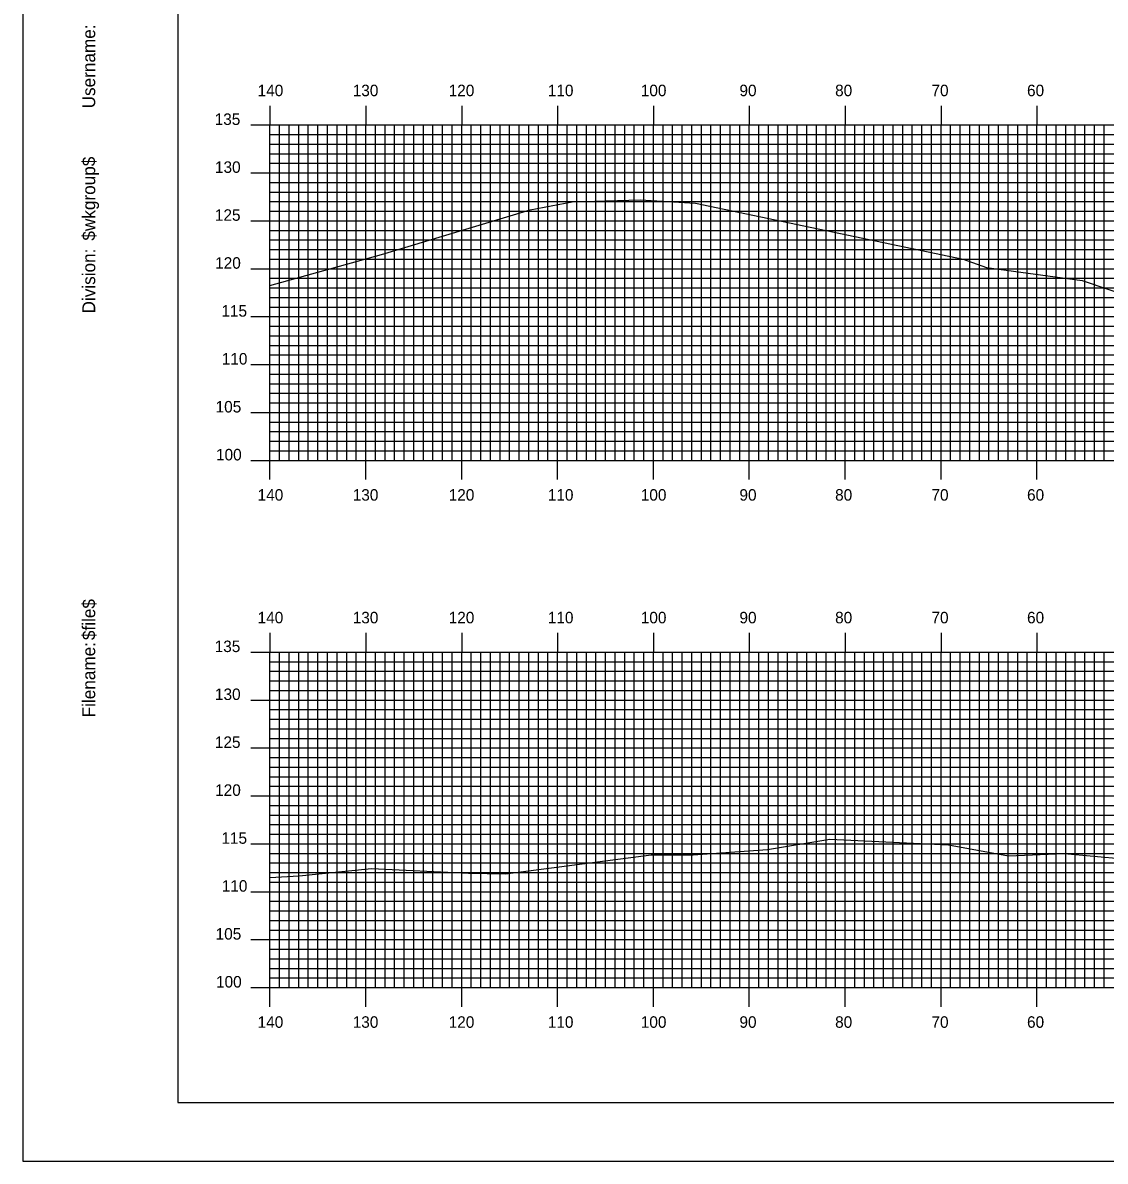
# Model space of a CAD drawing. Extents: x 1766513 to 1766856, y 442591 to 442811.
# Drawn here: x 1766513.1 to 1766626, y 442590.5 to 442709.3 of the extents above; entities that cross this region are included whole.
import ezdxf

# ---------------------------------------------------------------- set-up
doc = ezdxf.new("R2010")
doc.units = 0
for name, color, linetype in [('BORDER', 7, 'Continuous'), ('H_V ANNOTATION', 7, 'Continuous'), ('MAJOR', 7, 'Continuous'), ('MINOR', 7, 'Continuous'), ('PLOT BOUNDARY', 7, 'Continuous'), ('S_Roadway_Centerline', 7, 'Continuous')]:
    doc.layers.add(name, color=color, linetype=linetype)

msp = doc.modelspace()

# ---------------------------------------------------------------- linework, layer by layer
at = {"layer": 'BORDER'}
msp.add_lwpolyline([(1766529.31, 442596.67), (1766849.31, 442596.67), (1766849.31, 442806.67), (1766529.31, 442806.67)], close=True, dxfattribs=at)
at = {"layer": 'MAJOR'}
for p, q in [((1766538.91, 442700.67), (1766538.91, 442698.67)), ((1766548.91, 442700.67), (1766548.91, 442698.67)), ((1766558.91, 442700.67), (1766558.91, 442698.67)), ((1766568.91, 442700.67), (1766568.91, 442698.67)), ((1766578.91, 442700.67), (1766578.91, 442698.67)), ((1766588.91, 442700.67), (1766588.91, 442698.67)), ((1766598.91, 442700.67), (1766598.91, 442698.67)), ((1766608.91, 442700.67), (1766608.91, 442698.67)), ((1766618.91, 442700.67), (1766618.91, 442698.67)), ((1766536.91, 442698.67), (1766538.91, 442698.67)), ((1766538.91, 442698.67), (1766818.91, 442698.67)), ((1766538.91, 442663.67), (1766538.91, 442698.67)), ((1766538.91, 442663.67), (1766538.91, 442698.67)), ((1766538.91, 442698.67), (1766818.91, 442698.67)), ((1766548.91, 442663.67), (1766548.91, 442698.67)), ((1766558.91, 442663.67), (1766558.91, 442698.67)), ((1766568.91, 442663.67), (1766568.91, 442698.67)), ((1766578.91, 442663.67), (1766578.91, 442698.67)), ((1766588.91, 442663.67), (1766588.91, 442698.67)), ((1766598.91, 442663.67), (1766598.91, 442698.67)), ((1766608.91, 442663.67), (1766608.91, 442698.67)), ((1766618.91, 442663.67), (1766618.91, 442698.67)), ((1766536.91, 442693.67), (1766538.91, 442693.67)), ((1766538.91, 442693.67), (1766818.91, 442693.67)), ((1766536.91, 442688.67), (1766538.91, 442688.67)), ((1766538.91, 442688.67), (1766818.91, 442688.67)), ((1766536.91, 442683.67), (1766538.91, 442683.67)), ((1766538.91, 442683.67), (1766818.91, 442683.67)), ((1766536.91, 442678.67), (1766538.91, 442678.67)), ((1766538.91, 442678.67), (1766818.91, 442678.67)), ((1766536.91, 442673.67), (1766538.91, 442673.67)), ((1766538.91, 442673.67), (1766818.91, 442673.67)), ((1766536.91, 442668.67), (1766538.91, 442668.67)), ((1766538.91, 442668.67), (1766818.91, 442668.67)), ((1766536.91, 442663.67), (1766538.91, 442663.67)), ((1766538.91, 442663.67), (1766818.91, 442663.67)), ((1766538.91, 442663.67), (1766818.91, 442663.67)), ((1766538.91, 442661.66), (1766538.91, 442663.67)), ((1766548.91, 442661.66), (1766548.91, 442663.67)), ((1766558.91, 442661.66), (1766558.91, 442663.67)), ((1766568.91, 442661.66), (1766568.91, 442663.67)), ((1766578.91, 442661.66), (1766578.91, 442663.67)), ((1766588.91, 442661.66), (1766588.91, 442663.67)), ((1766598.91, 442661.66), (1766598.91, 442663.67)), ((1766608.91, 442661.66), (1766608.91, 442663.67)), ((1766618.91, 442661.66), (1766618.91, 442663.67)), ((1766538.91, 442645.67), (1766538.91, 442643.67)), ((1766548.91, 442645.67), (1766548.91, 442643.67)), ((1766558.91, 442645.67), (1766558.91, 442643.67)), ((1766568.91, 442645.67), (1766568.91, 442643.67)), ((1766578.91, 442645.67), (1766578.91, 442643.67)), ((1766588.91, 442645.67), (1766588.91, 442643.67)), ((1766598.91, 442645.67), (1766598.91, 442643.67)), ((1766608.91, 442645.67), (1766608.91, 442643.67)), ((1766618.91, 442645.67), (1766618.91, 442643.67)), ((1766536.91, 442643.67), (1766538.91, 442643.67)), ((1766538.91, 442643.67), (1766818.91, 442643.67)), ((1766538.91, 442608.67), (1766538.91, 442643.67)), ((1766538.91, 442608.67), (1766538.91, 442643.67)), ((1766538.91, 442643.67), (1766818.91, 442643.67)), ((1766548.91, 442608.67), (1766548.91, 442643.67)), ((1766558.91, 442608.67), (1766558.91, 442643.67)), ((1766568.91, 442608.67), (1766568.91, 442643.67)), ((1766578.91, 442608.67), (1766578.91, 442643.67)), ((1766588.91, 442608.67), (1766588.91, 442643.67)), ((1766598.91, 442608.67), (1766598.91, 442643.67)), ((1766608.91, 442608.67), (1766608.91, 442643.67)), ((1766618.91, 442608.67), (1766618.91, 442643.67)), ((1766536.91, 442638.67), (1766538.91, 442638.67)), ((1766538.91, 442638.67), (1766818.91, 442638.67)), ((1766536.91, 442633.67), (1766538.91, 442633.67)), ((1766538.91, 442633.67), (1766818.91, 442633.67)), ((1766536.91, 442628.67), (1766538.91, 442628.67)), ((1766538.91, 442628.67), (1766818.91, 442628.67)), ((1766536.91, 442623.67), (1766538.91, 442623.67)), ((1766538.91, 442623.67), (1766818.91, 442623.67)), ((1766536.91, 442618.67), (1766538.91, 442618.67)), ((1766538.91, 442618.67), (1766818.91, 442618.67)), ((1766536.91, 442613.67), (1766538.91, 442613.67)), ((1766538.91, 442613.67), (1766818.91, 442613.67)), ((1766536.91, 442608.67), (1766538.91, 442608.67)), ((1766538.91, 442608.67), (1766818.91, 442608.67)), ((1766538.91, 442608.67), (1766818.91, 442608.67)), ((1766538.91, 442606.66), (1766538.91, 442608.67)), ((1766548.91, 442606.66), (1766548.91, 442608.67)), ((1766558.91, 442606.66), (1766558.91, 442608.67)), ((1766568.91, 442606.66), (1766568.91, 442608.67)), ((1766578.91, 442606.66), (1766578.91, 442608.67)), ((1766588.91, 442606.66), (1766588.91, 442608.67)), ((1766598.91, 442606.66), (1766598.91, 442608.67)), ((1766608.91, 442606.66), (1766608.91, 442608.67)), ((1766618.91, 442606.66), (1766618.91, 442608.67))]:
    msp.add_line(p, q, dxfattribs=at)
at = {"layer": 'MINOR'}
for p, q in [((1766539.91, 442663.67), (1766539.91, 442698.67)), ((1766540.91, 442663.67), (1766540.91, 442698.67)), ((1766541.91, 442663.67), (1766541.91, 442698.67)), ((1766542.91, 442663.67), (1766542.91, 442698.67)), ((1766543.91, 442663.67), (1766543.91, 442698.67)), ((1766544.91, 442663.67), (1766544.91, 442698.67)), ((1766545.91, 442663.67), (1766545.91, 442698.67)), ((1766546.91, 442663.67), (1766546.91, 442698.67)), ((1766547.91, 442663.67), (1766547.91, 442698.67)), ((1766549.91, 442663.67), (1766549.91, 442698.67)), ((1766550.91, 442663.67), (1766550.91, 442698.67)), ((1766551.91, 442663.67), (1766551.91, 442698.67)), ((1766552.91, 442663.67), (1766552.91, 442698.67)), ((1766553.91, 442663.67), (1766553.91, 442698.67)), ((1766554.91, 442663.67), (1766554.91, 442698.67)), ((1766555.91, 442663.67), (1766555.91, 442698.67)), ((1766556.91, 442663.67), (1766556.91, 442698.67)), ((1766557.91, 442663.67), (1766557.91, 442698.67)), ((1766559.91, 442663.67), (1766559.91, 442698.67)), ((1766560.91, 442663.67), (1766560.91, 442698.67)), ((1766561.91, 442663.67), (1766561.91, 442698.67)), ((1766562.91, 442663.67), (1766562.91, 442698.67)), ((1766563.91, 442663.67), (1766563.91, 442698.67)), ((1766564.91, 442663.67), (1766564.91, 442698.67)), ((1766565.91, 442663.67), (1766565.91, 442698.67)), ((1766566.91, 442663.67), (1766566.91, 442698.67)), ((1766567.91, 442663.67), (1766567.91, 442698.67)), ((1766569.91, 442663.67), (1766569.91, 442698.67)), ((1766570.91, 442663.67), (1766570.91, 442698.67)), ((1766571.91, 442663.67), (1766571.91, 442698.67)), ((1766572.91, 442663.67), (1766572.91, 442698.67)), ((1766573.91, 442663.67), (1766573.91, 442698.67)), ((1766574.91, 442663.67), (1766574.91, 442698.67)), ((1766575.91, 442663.67), (1766575.91, 442698.67)), ((1766576.91, 442663.67), (1766576.91, 442698.67)), ((1766577.91, 442663.67), (1766577.91, 442698.67)), ((1766579.91, 442663.67), (1766579.91, 442698.67)), ((1766580.91, 442663.67), (1766580.91, 442698.67)), ((1766581.91, 442663.67), (1766581.91, 442698.67)), ((1766582.91, 442663.67), (1766582.91, 442698.67)), ((1766583.91, 442663.67), (1766583.91, 442698.67)), ((1766584.91, 442663.67), (1766584.91, 442698.67)), ((1766585.91, 442663.67), (1766585.91, 442698.67)), ((1766586.91, 442663.67), (1766586.91, 442698.67)), ((1766587.91, 442663.67), (1766587.91, 442698.67)), ((1766589.91, 442663.67), (1766589.91, 442698.67)), ((1766590.91, 442663.67), (1766590.91, 442698.67)), ((1766591.91, 442663.67), (1766591.91, 442698.67)), ((1766592.91, 442663.67), (1766592.91, 442698.67)), ((1766593.91, 442663.67), (1766593.91, 442698.67)), ((1766594.91, 442663.67), (1766594.91, 442698.67)), ((1766595.91, 442663.67), (1766595.91, 442698.67)), ((1766596.91, 442663.67), (1766596.91, 442698.67)), ((1766597.91, 442663.67), (1766597.91, 442698.67)), ((1766599.91, 442663.67), (1766599.91, 442698.67)), ((1766600.91, 442663.67), (1766600.91, 442698.67)), ((1766601.91, 442663.67), (1766601.91, 442698.67)), ((1766602.91, 442663.67), (1766602.91, 442698.67)), ((1766603.91, 442663.67), (1766603.91, 442698.67)), ((1766604.91, 442663.67), (1766604.91, 442698.67)), ((1766605.91, 442663.67), (1766605.91, 442698.67)), ((1766606.91, 442663.67), (1766606.91, 442698.67)), ((1766607.91, 442663.67), (1766607.91, 442698.67)), ((1766609.91, 442663.67), (1766609.91, 442698.67)), ((1766610.91, 442663.67), (1766610.91, 442698.67)), ((1766611.91, 442663.67), (1766611.91, 442698.67)), ((1766612.91, 442663.67), (1766612.91, 442698.67)), ((1766613.91, 442663.67), (1766613.91, 442698.67)), ((1766614.91, 442663.67), (1766614.91, 442698.67)), ((1766615.91, 442663.67), (1766615.91, 442698.67)), ((1766616.91, 442663.67), (1766616.91, 442698.67)), ((1766617.91, 442663.67), (1766617.91, 442698.67)), ((1766619.91, 442663.67), (1766619.91, 442698.67)), ((1766620.91, 442663.67), (1766620.91, 442698.67)), ((1766621.91, 442663.67), (1766621.91, 442698.67)), ((1766622.91, 442663.67), (1766622.91, 442698.67)), ((1766623.91, 442663.67), (1766623.91, 442698.67)), ((1766624.91, 442663.67), (1766624.91, 442698.67)), ((1766625.91, 442663.67), (1766625.91, 442698.67)), ((1766538.91, 442697.67), (1766818.91, 442697.67)), ((1766538.91, 442697.67), (1766540.91, 442697.67)), ((1766538.91, 442696.67), (1766818.91, 442696.67)), ((1766538.91, 442696.67), (1766540.91, 442696.67)), ((1766538.91, 442695.67), (1766818.91, 442695.67)), ((1766538.91, 442695.67), (1766540.91, 442695.67)), ((1766538.91, 442694.67), (1766818.91, 442694.67)), ((1766538.91, 442694.67), (1766540.91, 442694.67)), ((1766538.91, 442692.67), (1766818.91, 442692.67)), ((1766538.91, 442692.67), (1766540.91, 442692.67)), ((1766538.91, 442691.67), (1766818.91, 442691.67)), ((1766538.91, 442691.67), (1766540.91, 442691.67)), ((1766538.91, 442690.67), (1766818.91, 442690.67)), ((1766538.91, 442690.67), (1766540.91, 442690.67)), ((1766538.91, 442689.67), (1766818.91, 442689.67)), ((1766538.91, 442689.67), (1766540.91, 442689.67)), ((1766538.91, 442687.67), (1766818.91, 442687.67)), ((1766538.91, 442687.67), (1766540.91, 442687.67)), ((1766538.91, 442686.67), (1766818.91, 442686.67)), ((1766538.91, 442686.67), (1766540.91, 442686.67)), ((1766538.91, 442685.67), (1766818.91, 442685.67)), ((1766538.91, 442685.67), (1766540.91, 442685.67)), ((1766538.91, 442684.67), (1766818.91, 442684.67)), ((1766538.91, 442684.67), (1766540.91, 442684.67)), ((1766538.91, 442682.67), (1766818.91, 442682.67)), ((1766538.91, 442682.67), (1766540.91, 442682.67)), ((1766538.91, 442681.67), (1766818.91, 442681.67)), ((1766538.91, 442681.67), (1766540.91, 442681.67)), ((1766538.91, 442680.67), (1766818.91, 442680.67)), ((1766538.91, 442680.67), (1766540.91, 442680.67)), ((1766538.91, 442679.67), (1766818.91, 442679.67)), ((1766538.91, 442679.67), (1766540.91, 442679.67)), ((1766538.91, 442677.67), (1766818.91, 442677.67)), ((1766538.91, 442677.67), (1766540.91, 442677.67)), ((1766538.91, 442676.67), (1766818.91, 442676.67)), ((1766538.91, 442676.67), (1766540.91, 442676.67)), ((1766538.91, 442675.67), (1766818.91, 442675.67)), ((1766538.91, 442675.67), (1766540.91, 442675.67)), ((1766538.91, 442674.67), (1766818.91, 442674.67)), ((1766538.91, 442674.67), (1766540.91, 442674.67)), ((1766538.91, 442672.67), (1766818.91, 442672.67)), ((1766538.91, 442672.67), (1766540.91, 442672.67)), ((1766538.91, 442671.67), (1766818.91, 442671.67)), ((1766538.91, 442671.67), (1766540.91, 442671.67)), ((1766538.91, 442670.67), (1766818.91, 442670.67)), ((1766538.91, 442670.67), (1766540.91, 442670.67)), ((1766538.91, 442669.67), (1766818.91, 442669.67)), ((1766538.91, 442669.67), (1766540.91, 442669.67)), ((1766538.91, 442667.67), (1766818.91, 442667.67)), ((1766538.91, 442667.67), (1766540.91, 442667.67)), ((1766538.91, 442666.67), (1766818.91, 442666.67)), ((1766538.91, 442666.67), (1766540.91, 442666.67)), ((1766538.91, 442665.67), (1766818.91, 442665.67)), ((1766538.91, 442665.67), (1766540.91, 442665.67)), ((1766538.91, 442664.67), (1766818.91, 442664.67)), ((1766538.91, 442664.67), (1766540.91, 442664.67)), ((1766539.91, 442608.67), (1766539.91, 442643.67)), ((1766540.91, 442608.67), (1766540.91, 442643.67)), ((1766541.91, 442608.67), (1766541.91, 442643.67)), ((1766542.91, 442608.67), (1766542.91, 442643.67)), ((1766543.91, 442608.67), (1766543.91, 442643.67)), ((1766544.91, 442608.67), (1766544.91, 442643.67)), ((1766545.91, 442608.67), (1766545.91, 442643.67)), ((1766546.91, 442608.67), (1766546.91, 442643.67)), ((1766547.91, 442608.67), (1766547.91, 442643.67)), ((1766549.91, 442608.67), (1766549.91, 442643.67)), ((1766550.91, 442608.67), (1766550.91, 442643.67)), ((1766551.91, 442608.67), (1766551.91, 442643.67)), ((1766552.91, 442608.67), (1766552.91, 442643.67)), ((1766553.91, 442608.67), (1766553.91, 442643.67)), ((1766554.91, 442608.67), (1766554.91, 442643.67)), ((1766555.91, 442608.67), (1766555.91, 442643.67)), ((1766556.91, 442608.67), (1766556.91, 442643.67)), ((1766557.91, 442608.67), (1766557.91, 442643.67)), ((1766559.91, 442608.67), (1766559.91, 442643.67)), ((1766560.91, 442608.67), (1766560.91, 442643.67)), ((1766561.91, 442608.67), (1766561.91, 442643.67)), ((1766562.91, 442608.67), (1766562.91, 442643.67)), ((1766563.91, 442608.67), (1766563.91, 442643.67)), ((1766564.91, 442608.67), (1766564.91, 442643.67)), ((1766565.91, 442608.67), (1766565.91, 442643.67)), ((1766566.91, 442608.67), (1766566.91, 442643.67)), ((1766567.91, 442608.67), (1766567.91, 442643.67)), ((1766569.91, 442608.67), (1766569.91, 442643.67)), ((1766570.91, 442608.67), (1766570.91, 442643.67)), ((1766571.91, 442608.67), (1766571.91, 442643.67)), ((1766572.91, 442608.67), (1766572.91, 442643.67)), ((1766573.91, 442608.67), (1766573.91, 442643.67)), ((1766574.91, 442608.67), (1766574.91, 442643.67)), ((1766575.91, 442608.67), (1766575.91, 442643.67)), ((1766576.91, 442608.67), (1766576.91, 442643.67)), ((1766577.91, 442608.67), (1766577.91, 442643.67)), ((1766579.91, 442608.67), (1766579.91, 442643.67)), ((1766580.91, 442608.67), (1766580.91, 442643.67)), ((1766581.91, 442608.67), (1766581.91, 442643.67)), ((1766582.91, 442608.67), (1766582.91, 442643.67)), ((1766583.91, 442608.67), (1766583.91, 442643.67)), ((1766584.91, 442608.67), (1766584.91, 442643.67)), ((1766585.91, 442608.67), (1766585.91, 442643.67)), ((1766586.91, 442608.67), (1766586.91, 442643.67)), ((1766587.91, 442608.67), (1766587.91, 442643.67)), ((1766589.91, 442608.67), (1766589.91, 442643.67)), ((1766590.91, 442608.67), (1766590.91, 442643.67)), ((1766591.91, 442608.67), (1766591.91, 442643.67)), ((1766592.91, 442608.67), (1766592.91, 442643.67)), ((1766593.91, 442608.67), (1766593.91, 442643.67)), ((1766594.91, 442608.67), (1766594.91, 442643.67)), ((1766595.91, 442608.67), (1766595.91, 442643.67)), ((1766596.91, 442608.67), (1766596.91, 442643.67)), ((1766597.91, 442608.67), (1766597.91, 442643.67)), ((1766599.91, 442608.67), (1766599.91, 442643.67)), ((1766600.91, 442608.67), (1766600.91, 442643.67)), ((1766601.91, 442608.67), (1766601.91, 442643.67)), ((1766602.91, 442608.67), (1766602.91, 442643.67)), ((1766603.91, 442608.67), (1766603.91, 442643.67)), ((1766604.91, 442608.67), (1766604.91, 442643.67)), ((1766605.91, 442608.67), (1766605.91, 442643.67)), ((1766606.91, 442608.67), (1766606.91, 442643.67)), ((1766607.91, 442608.67), (1766607.91, 442643.67)), ((1766609.91, 442608.67), (1766609.91, 442643.67)), ((1766610.91, 442608.67), (1766610.91, 442643.67)), ((1766611.91, 442608.67), (1766611.91, 442643.67)), ((1766612.91, 442608.67), (1766612.91, 442643.67)), ((1766613.91, 442608.67), (1766613.91, 442643.67)), ((1766614.91, 442608.67), (1766614.91, 442643.67)), ((1766615.91, 442608.67), (1766615.91, 442643.67)), ((1766616.91, 442608.67), (1766616.91, 442643.67)), ((1766617.91, 442608.67), (1766617.91, 442643.67)), ((1766619.91, 442608.67), (1766619.91, 442643.67)), ((1766620.91, 442608.67), (1766620.91, 442643.67)), ((1766621.91, 442608.67), (1766621.91, 442643.67)), ((1766622.91, 442608.67), (1766622.91, 442643.67)), ((1766623.91, 442608.67), (1766623.91, 442643.67)), ((1766624.91, 442608.67), (1766624.91, 442643.67)), ((1766625.91, 442608.67), (1766625.91, 442643.67)), ((1766538.91, 442642.67), (1766818.91, 442642.67)), ((1766538.91, 442642.67), (1766540.91, 442642.67)), ((1766538.91, 442641.67), (1766818.91, 442641.67)), ((1766538.91, 442641.67), (1766540.91, 442641.67)), ((1766538.91, 442640.67), (1766818.91, 442640.67)), ((1766538.91, 442640.67), (1766540.91, 442640.67)), ((1766538.91, 442639.67), (1766818.91, 442639.67)), ((1766538.91, 442639.67), (1766540.91, 442639.67)), ((1766538.91, 442637.67), (1766818.91, 442637.67)), ((1766538.91, 442637.67), (1766540.91, 442637.67)), ((1766538.91, 442636.67), (1766818.91, 442636.67)), ((1766538.91, 442636.67), (1766540.91, 442636.67)), ((1766538.91, 442635.67), (1766818.91, 442635.67)), ((1766538.91, 442635.67), (1766540.91, 442635.67)), ((1766538.91, 442634.67), (1766818.91, 442634.67)), ((1766538.91, 442634.67), (1766540.91, 442634.67)), ((1766538.91, 442632.67), (1766818.91, 442632.67)), ((1766538.91, 442632.67), (1766540.91, 442632.67)), ((1766538.91, 442631.67), (1766818.91, 442631.67)), ((1766538.91, 442631.67), (1766540.91, 442631.67)), ((1766538.91, 442630.67), (1766818.91, 442630.67)), ((1766538.91, 442630.67), (1766540.91, 442630.67)), ((1766538.91, 442629.67), (1766818.91, 442629.67)), ((1766538.91, 442629.67), (1766540.91, 442629.67)), ((1766538.91, 442627.67), (1766818.91, 442627.67)), ((1766538.91, 442627.67), (1766540.91, 442627.67)), ((1766538.91, 442626.67), (1766818.91, 442626.67)), ((1766538.91, 442626.67), (1766540.91, 442626.67)), ((1766538.91, 442625.67), (1766818.91, 442625.67)), ((1766538.91, 442625.67), (1766540.91, 442625.67)), ((1766538.91, 442624.67), (1766818.91, 442624.67)), ((1766538.91, 442624.67), (1766540.91, 442624.67)), ((1766538.91, 442622.67), (1766818.91, 442622.67)), ((1766538.91, 442622.67), (1766540.91, 442622.67)), ((1766538.91, 442621.67), (1766818.91, 442621.67)), ((1766538.91, 442621.67), (1766540.91, 442621.67)), ((1766538.91, 442620.67), (1766818.91, 442620.67)), ((1766538.91, 442620.67), (1766540.91, 442620.67)), ((1766538.91, 442619.67), (1766818.91, 442619.67)), ((1766538.91, 442619.67), (1766540.91, 442619.67)), ((1766538.91, 442617.67), (1766818.91, 442617.67)), ((1766538.91, 442617.67), (1766540.91, 442617.67)), ((1766538.91, 442616.67), (1766818.91, 442616.67)), ((1766538.91, 442616.67), (1766540.91, 442616.67)), ((1766538.91, 442615.67), (1766818.91, 442615.67)), ((1766538.91, 442615.67), (1766540.91, 442615.67)), ((1766538.91, 442614.67), (1766818.91, 442614.67)), ((1766538.91, 442614.67), (1766540.91, 442614.67)), ((1766538.91, 442612.67), (1766818.91, 442612.67)), ((1766538.91, 442612.67), (1766540.91, 442612.67)), ((1766538.91, 442611.67), (1766818.91, 442611.67)), ((1766538.91, 442611.67), (1766540.91, 442611.67)), ((1766538.91, 442610.67), (1766818.91, 442610.67)), ((1766538.91, 442610.67), (1766540.91, 442610.67)), ((1766538.91, 442609.67), (1766818.91, 442609.67)), ((1766538.91, 442609.67), (1766540.91, 442609.67))]:
    msp.add_line(p, q, dxfattribs=at)
at = {"layer": 'PLOT BOUNDARY'}
msp.add_lwpolyline([(1766513.12, 442590.55), (1766853.12, 442590.55), (1766853.12, 442810.55), (1766513.12, 442810.55)], close=True, dxfattribs=at)
at = {"layer": 'S_Roadway_Centerline'}
for points in [[(1766538.91, 442681.91), (1766550.53, 442685.15), (1766566.04, 442689.81), (1766570.42, 442690.66), (1766577.54, 442690.86), (1766583.28, 442690.52), (1766611.21, 442684.66), (1766613.65, 442683.81), (1766623.63, 442682.44), (1766637.21, 442677.84)], [(1766538.91, 442620.15), (1766541.96, 442620.31), (1766549.5, 442621.1), (1766559.63, 442620.59), (1766563.48, 442620.52), (1766578.66, 442622.53), (1766583.04, 442622.53), (1766590.8, 442623.07), (1766597.31, 442624.15), (1766609.7, 442623.56), (1766615.96, 442622.41), (1766621.75, 442622.67), (1766634.14, 442621.54)]]:
    msp.add_lwpolyline(points, dxfattribs=at)

# ---------------------------------------------------------------- texts
at = {"layer": 'BORDER'}
for s, p in [('Username:', (1766520.68, 442700.4)), ('$wkgroup$', (1766520.68, 442686.6)), ('Division:', (1766520.68, 442679)), ('$file$', (1766520.68, 442644.92)), ('Filename:', (1766520.68, 442636.86))]:
    msp.add_text(s, height=1.339, rotation=90, dxfattribs=at).set_placement(p)
at = {"layer": 'H_V ANNOTATION'}
for s, p in [('140', (1766537.62, 442701.67)), ('130', (1766547.54, 442701.67)), ('120', (1766557.55, 442701.67)), ('110', (1766567.89, 442701.67)), ('100', (1766577.59, 442701.67)), ('90', (1766587.88, 442701.67)), ('80', (1766597.86, 442701.67)), ('70', (1766607.91, 442701.67)), ('60', (1766617.88, 442701.67)), ('135', (1766533.14, 442698.67)), ('130', (1766533.17, 442693.67)), ('125', (1766533.16, 442688.67)), ('120', (1766533.19, 442683.67)), ('115', (1766533.84, 442678.67)), ('110', (1766533.88, 442673.67)), ('105', (1766533.24, 442668.67)), ('100', (1766533.28, 442663.67)), ('140', (1766537.62, 442659.47)), ('130', (1766547.54, 442659.47)), ('120', (1766557.55, 442659.47)), ('110', (1766567.89, 442659.47)), ('100', (1766577.59, 442659.47)), ('90', (1766587.88, 442659.47)), ('80', (1766597.86, 442659.47)), ('70', (1766607.91, 442659.47)), ('60', (1766617.88, 442659.47)), ('140', (1766537.62, 442646.67)), ('130', (1766547.54, 442646.67)), ('120', (1766557.55, 442646.67)), ('110', (1766567.89, 442646.67)), ('100', (1766577.59, 442646.67)), ('90', (1766587.88, 442646.67)), ('80', (1766597.86, 442646.67)), ('70', (1766607.91, 442646.67)), ('60', (1766617.88, 442646.67)), ('135', (1766533.14, 442643.67)), ('130', (1766533.17, 442638.67)), ('125', (1766533.16, 442633.67)), ('120', (1766533.19, 442628.67)), ('115', (1766533.84, 442623.67)), ('110', (1766533.88, 442618.67)), ('105', (1766533.24, 442613.67)), ('100', (1766533.28, 442608.67)), ('140', (1766537.62, 442604.47)), ('130', (1766547.54, 442604.47)), ('120', (1766557.55, 442604.47)), ('110', (1766567.89, 442604.47)), ('100', (1766577.59, 442604.47)), ('90', (1766587.88, 442604.47)), ('80', (1766597.86, 442604.47)), ('70', (1766607.91, 442604.47)), ('60', (1766617.88, 442604.47))]:
    msp.add_text(s, height=1.2, dxfattribs=at).set_placement(p)
at = {"layer": 'MAJOR'}
for p in [(1766538.9, 442663.67), (1766538.9, 442608.67)]:
    msp.add_text('-', height=0.012, dxfattribs=at).set_placement(p)

doc.saveas('drawing.dxf')
